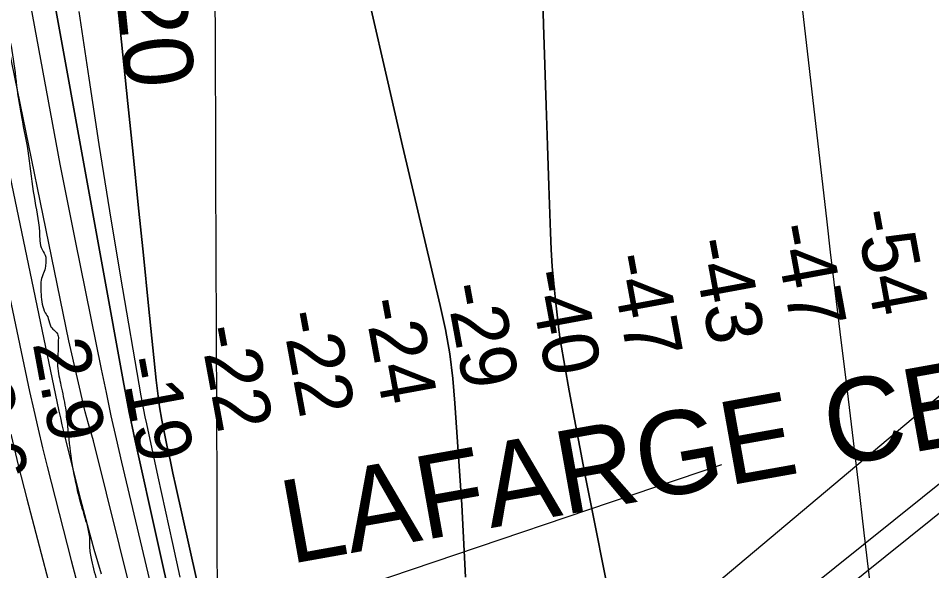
# Model space of a CAD drawing. Extents: x 3392644 to 3430565, y 576657 to 602123.
# Drawn here: x 3412346 to 3413444, y 583022 to 583686 of the extents above; entities that cross this region are included whole.
import ezdxf

# ---------------------------------------------------------------- set-up
doc = ezdxf.new("R2010")
doc.units = 0
for name, color, linetype in [('V-CHAN-NAID', 7, 'Continuous'), ('V-GRID-MAJR', 7, 'Continuous'), ('V-RIVR-EDGE', 7, 'Continuous'), ('V-RIVR-RANG', 7, 'Continuous'), ('V-TOPO-DPTH', 7, 'Continuous'), ('V-TOPO-MAJR', 7, 'Continuous'), ('V-TOPO-MINR', 7, 'Continuous'), ('V-TOPO-MINR-IDEN', 7, 'Continuous'), ('V-TOPO-WATR', 7, 'Continuous'), ('V-UTIL-LINE', 7, 'Continuous')]:
    doc.layers.add(name, color=color, linetype=linetype)

msp = doc.modelspace()

# ---------------------------------------------------------------- linework, layer by layer
at = {"layer": 'V-GRID-MAJR'}
msp.add_spline([(3412589.1, 582101.8), (3412567.1, 588159.5), (3412545, 594220.6), (3412523, 600281.7), (3412523, 600285.2)], degree=3, dxfattribs=at)
at = {"layer": 'V-RIVR-EDGE'}
msp.add_spline([(3412059.2, 585196.3), (3412062.1, 585176.5), (3412061.7, 585167.8), (3412066, 585148), (3412070, 585133.8), (3412072.2, 585119.1), (3412074.7, 585110.4), (3412079.8, 585095.7), (3412081.2, 585089.5), (3412079.7, 585078.5), (3412079.4, 585072.3), (3412081.2, 585067.6), (3412084.5, 585067.2), (3412095.1, 585068.6), (3412098.7, 585067.5), (3412101.3, 585058.4), (3412103.4, 585032.4), (3412101.6, 585030.2), (3412098.6, 585028.4), (3412097.5, 585027.3), (3412097.5, 585024.4), (3412103, 585018.2), (3412107.7, 585007.2), (3412106.9, 584977.9), (3412102.8, 584958.6), (3412103.5, 584940.3), (3412103.5, 584934.1), (3412107.1, 584926.4), (3412113, 584923.8), (3412115.5, 584916.5), (3412114.8, 584908.5), (3412113.7, 584905.5), (3412117.3, 584901.2), (3412119.9, 584893.8), (3412124.2, 584870.8), (3412130.7, 584830.9), (3412135.7, 584804.6), (3412137.9, 584792.5), (3412134.9, 584783.4), (3412138.1, 584748.3), (3412137, 584737.7), (3412137.3, 584723.4), (3412141.7, 584704.8), (3412149.7, 584674.1), (3412155.4, 584639.3), (3412160.8, 584615.2), (3412165.2, 584590.3), (3412166.2, 584579.7), (3412169.1, 584565.1), (3412169.1, 584558.5), (3412167.6, 584554.9), (3412164.3, 584551.9), (3412166.9, 584533.3), (3412168.3, 584519), (3412171.2, 584502.2), (3412177.3, 584467.8), (3412184.2, 584443.7), (3412191.4, 584410), (3412199.7, 584367.6), (3412203.6, 584329.2), (3412206.8, 584289), (3412206.4, 584269.3), (3412208.9, 584247.7), (3412213.6, 584217), (3412216.5, 584210.4), (3412220.9, 584204.5), (3412226.7, 584202.3), (3412230.4, 584203.8), (3412233.3, 584201.6), (3412234.4, 584193.5), (3412234, 584192.1), (3412230.3, 584190.6), (3412233.2, 584174.2), (3412237.9, 584149.7), (3412243.7, 584125.5), (3412251, 584099.5), (3412250.9, 584093.7), (3412249.1, 584083.5), (3412250.2, 584076.1), (3412275.2, 584001.5), (3412285.3, 583961.3), (3412288.9, 583930.6), (3412290.3, 583910.1), (3412289.2, 583900.2), (3412292.1, 583879.4), (3412299.3, 583856.3), (3412308, 583829.3), (3412312.7, 583799.3), (3412319.2, 583750.6), (3412321, 583731.3), (3412329.3, 583686.6), (3412338.7, 583647.1), (3412344.4, 583604.4), (3412350.2, 583567.4), (3412358.8, 583520.6), (3412365.3, 583471.6), (3412371.8, 583429.2), (3412375, 583408), (3412379.4, 583398.8), (3412379.3, 583391.2), (3412379, 583387.9), (3412376.8, 583379.8), (3412374.9, 583375.4), (3412373.4, 583366.7), (3412373.8, 583353.9), (3412378.8, 583331.9), (3412382.5, 583325.3), (3412385.7, 583315.1), (3412394.1, 583305.2), (3412394.5, 583299.7), (3412394.4, 583288), (3412393.7, 583278.5), (3412393.7, 583267.9), (3412397.6, 583244.9), (3412403, 583217.8), (3412407.7, 583175), (3412422.1, 583100.4), (3412429, 583076.7), (3412431.9, 583060.6), (3412431.9, 583051.4), (3412434.4, 583035), (3412441.6, 583007.5), (3412451.4, 582962.9), (3412455.4, 582943.9), (3412459, 582941.3), (3412460.5, 582932.2), (3412468.4, 582890.5), (3412469.1, 582885.4), (3412468.4, 582884.6), (3412464, 582883.9), (3412461.8, 582881), (3412462.1, 582876.6), (3412467.6, 582853.2), (3412470.5, 582841.1), (3412473.7, 582838.2), (3412477, 582835.3), (3412479.9, 582822.5), (3412500.5, 582724.5), (3412513.2, 582674), (3412526.2, 582618), (3412557.1, 582528), (3412580.3, 582453), (3412593.3, 582406.6), (3412604.9, 582372.5), (3412613.6, 582344), (3412619.4, 582324.3), (3412630, 582308.1), (3412635.4, 582288.8), (3412638.3, 582277.4), (3412649.2, 582259.8), (3412659, 582231.7), (3412668.5, 582210.1), (3412681.6, 582191.4), (3412693.6, 582172), (3412707.8, 582126.3), (3412708.4, 582107.6), (3412708, 582102.2)], degree=3, dxfattribs=at)
at = {"layer": 'V-RIVR-RANG'}
msp.add_line((3412054.7, 582765.8), (3413191.7, 583149.7), dxfattribs=at)
at = {"layer": 'V-TOPO-DPTH'}
for points in [[(3412436.8, 583985.3), (3412478.2, 583583.4), (3412484.4, 583522.7), (3412490.6, 583461.9), (3412496.8, 583401.1), (3412503, 583340.4), (3412512, 583251.1), (3412513.9, 583235), (3412516.1, 583218.9), (3412518.8, 583203), (3412521.9, 583187.1), (3412525.3, 583171.2), (3412528.7, 583155.3), (3412532.2, 583139.5), (3412535.7, 583123.6), (3412686.5, 582449.5)], [(3412686.5, 582449.5), (3412535.7, 583123.6), (3412532.2, 583139.5), (3412528.7, 583155.3), (3412525.3, 583171.2), (3412521.9, 583187.1), (3412518.8, 583203), (3412516.1, 583218.9), (3412513.9, 583235), (3412512, 583251.1), (3412503, 583340.4), (3412496.8, 583401.1), (3412490.6, 583461.9), (3412484.4, 583522.7), (3412478.2, 583583.4), (3412436.8, 583985.3)], [(3412748.8, 582102.4), (3412725.9, 582179.9), (3412702.6, 582264.6), (3412668.6, 582394.9), (3412663.5, 582414.8), (3412658.5, 582434.7), (3412653.6, 582454.7), (3412648.9, 582474.7), (3412584.5, 582747.9), (3412566.4, 582825.1), (3412548.6, 582902.5), (3412531, 582979.9), (3412513.7, 583057.3), (3412486.9, 583178.3), (3412483.2, 583195.3), (3412479.7, 583212.3), (3412476.4, 583229.4), (3412473.2, 583246.5), (3412345.3, 583950.1)], [(3412345.3, 583950.1), (3412473.2, 583246.5), (3412476.4, 583229.4), (3412479.7, 583212.3), (3412483.2, 583195.3), (3412486.9, 583178.3), (3412513.7, 583057.3), (3412531, 582979.9), (3412548.6, 582902.5), (3412566.4, 582825.1), (3412584.5, 582747.9), (3412648.9, 582474.7), (3412653.6, 582454.7), (3412658.5, 582434.7), (3412663.5, 582414.8), (3412668.6, 582394.9), (3412702.6, 582264.6), (3412725.9, 582179.9), (3412748.8, 582102.4)], [(3412973.2, 583830.3), (3412977.6, 583678.1), (3412979, 583629.7), (3412980.5, 583581.2), (3412982.1, 583532.8), (3412983.8, 583484.4), (3412985.8, 583428.4), (3412986.8, 583408), (3412988.1, 583387.7), (3412989.8, 583367.3), (3412991.9, 583347.1), (3412995.4, 583315.6), (3412996, 583311.1), (3412996.6, 583306.5), (3412997.3, 583302), (3412998, 583297.5), (3413008.5, 583238.5), (3413014.7, 583204.4), (3413021, 583170.5), (3413027.5, 583136.5), (3413034.2, 583102.6), (3413140.7, 582570)], [(3412973.2, 583830.3), (3412977.6, 583678.1), (3412979, 583629.7), (3412980.5, 583581.2), (3412982.1, 583532.8), (3412983.8, 583484.4), (3412985.8, 583428.4), (3412986.8, 583408), (3412988.1, 583387.7), (3412989.8, 583367.3), (3412991.9, 583347.1), (3412995.4, 583315.6), (3412996, 583311.1), (3412996.6, 583306.5), (3412997.3, 583302), (3412998, 583297.5), (3413008.5, 583238.5), (3413014.7, 583204.4), (3413021, 583170.5), (3413027.5, 583136.5), (3413034.2, 583102.6), (3413140.7, 582570)], [(3412770.3, 583696.4), (3412789.1, 583614.5), (3412808.1, 583532.6), (3412853.5, 583340.9), (3412859.7, 583311.8), (3412864.8, 583282.6), (3412868.5, 583253.2), (3412871.1, 583223.6), (3412879.2, 583101.5), (3412883.8, 583014.7)], [(3412883.8, 583014.7), (3412879.2, 583101.5), (3412871.1, 583223.6), (3412868.5, 583253.2), (3412864.8, 583282.6), (3412859.7, 583311.8), (3412853.5, 583340.9), (3412808.1, 583532.6), (3412789.1, 583614.5), (3412770.3, 583696.4)], [(3412708.5, 582102.3), (3412704.9, 582116.7), (3412663.6, 582281.1), (3412624.8, 582431.1), (3412605.4, 582511.1), (3412570.8, 582654.3), (3412499.1, 582926.9), (3412436.8, 583178.2), (3412430.9, 583198.7), (3412426.6, 583213.2), (3412407.3, 583298.3), (3412328.2, 583683.4)], [(3412708.5, 582102.3), (3412704.9, 582116.7), (3412663.6, 582281.1), (3412624.8, 582431.1), (3412605.4, 582511.1), (3412570.8, 582654.3), (3412499.1, 582926.9), (3412436.8, 583178.2), (3412430.9, 583198.7), (3412426.6, 583213.2), (3412407.3, 583298.3), (3412328.2, 583683.4)], [(3412305.4, 583494.8), (3412360, 583237.5), (3412365, 583214.9), (3412370.1, 583192.4), (3412375.5, 583169.9), (3412381.1, 583147.4), (3412410, 583034.5), (3412430.7, 582955.7), (3412451.9, 582877.1), (3412473.9, 582798.7), (3412496.5, 582720.5), (3412564.9, 582488.3), (3412574.4, 582455.7), (3412583.7, 582422.9), (3412592.7, 582390.1), (3412601.5, 582357.2), (3412610, 582324.3), (3412618.4, 582291.3), (3412626.6, 582258.3), (3412634.7, 582225.2), (3412664.4, 582102.1)]]:
    msp.add_lwpolyline(points, dxfattribs=at)
at = {"layer": 'V-TOPO-MAJR'}
msp.add_lwpolyline([(3413370.1, 583007.5), (3413363, 583067.7), (3413355.9, 583127.9), (3413348.7, 583188.1), (3413341.4, 583248.3), (3413335.6, 583296), (3413331.2, 583332.3), (3413326.8, 583368.7), (3413322.5, 583405), (3413318.3, 583441.3), (3413255.7, 583983.5)], dxfattribs=at)
at = {"layer": 'V-TOPO-MINR'}
for points in [[(3412436.8, 583985.3), (3412478.2, 583583.4), (3412484.4, 583522.7), (3412490.6, 583461.9), (3412496.8, 583401.1), (3412503, 583340.4), (3412512, 583251.1), (3412513.9, 583235), (3412516.1, 583218.9), (3412518.8, 583203), (3412521.9, 583187.1), (3412525.3, 583171.2), (3412528.7, 583155.3), (3412532.2, 583139.5), (3412535.7, 583123.6), (3412686.5, 582449.5)], [(3412345.3, 583950.1), (3412473.2, 583246.5), (3412476.4, 583229.4), (3412479.7, 583212.3), (3412483.2, 583195.3), (3412486.9, 583178.3), (3412513.7, 583057.3), (3412531, 582979.9), (3412548.6, 582902.5), (3412566.4, 582825.1), (3412584.5, 582747.9), (3412648.9, 582474.7), (3412653.6, 582454.7), (3412658.5, 582434.7), (3412663.5, 582414.8), (3412668.6, 582394.9), (3412702.6, 582264.6), (3412725.9, 582179.9), (3412748.8, 582102.4)], [(3412250.5, 583906.5), (3412395.3, 583213.9), (3412397.1, 583205.8), (3412398.9, 583197.6), (3412400.8, 583189.5), (3412402.8, 583181.3), (3412413.6, 583137.7), (3412421.3, 583107.8), (3412429.1, 583077.9), (3412437.3, 583048.2), (3412445.8, 583018.5)], [(3413140.7, 582570), (3413034.2, 583102.6), (3413027.5, 583136.5), (3413021, 583170.5), (3413014.7, 583204.4), (3413008.5, 583238.5), (3412998, 583297.5), (3412997.3, 583302), (3412996.6, 583306.5), (3412996, 583311.1), (3412995.4, 583315.6), (3412991.9, 583347.1), (3412989.8, 583367.3), (3412988.1, 583387.7), (3412986.8, 583408), (3412985.8, 583428.4), (3412983.8, 583484.4), (3412982.1, 583532.8), (3412980.5, 583581.2), (3412979, 583629.7), (3412977.6, 583678.1), (3412973.2, 583830.3)], [(3412345.2, 583788.2), (3412396.4, 583510.6), (3412414.7, 583418.3), (3412446, 583264.2), (3412451.8, 583236.3), (3412457.8, 583208.4), (3412464.1, 583180.5), (3412470.6, 583152.7), (3412524.6, 582924.7), (3412544.1, 582842.6), (3412563.7, 582760.5), (3412583.3, 582678.4), (3412603.1, 582596.4), (3412629.3, 582487.6), (3412636, 582459.9), (3412642.8, 582432.3), (3412649.8, 582404.7), (3412656.8, 582377.1), (3412713.8, 582156.6), (3412728.4, 582102.3)], [(3412419.3, 583693.8), (3412431.1, 583613.9), (3412443.3, 583534.1), (3412456.2, 583454.3), (3412469.4, 583374.7), (3412493.7, 583232.4), (3412495.2, 583223.9), (3412496.8, 583215.4), (3412498.5, 583207), (3412500.3, 583198.6), (3412514, 583135.1), (3412522.8, 583094.9), (3412531.7, 583054.8), (3412540.7, 583014.7)], [(3412770.3, 583696.4), (3412789.1, 583614.5), (3412808.1, 583532.6), (3412853.5, 583340.9), (3412859.7, 583311.8), (3412864.8, 583282.6), (3412868.5, 583253.2), (3412871.1, 583223.6), (3412879.2, 583101.5), (3412883.8, 583014.7)], [(3412305.4, 583494.8), (3412360, 583237.5), (3412365, 583214.9), (3412370.1, 583192.4), (3412375.5, 583169.9), (3412381.1, 583147.4), (3412410, 583034.5), (3412430.7, 582955.7), (3412451.9, 582877.1), (3412473.9, 582798.7), (3412496.5, 582720.5), (3412564.9, 582488.3), (3412574.4, 582455.7), (3412583.7, 582422.9), (3412592.7, 582390.1), (3412601.5, 582357.2), (3412610, 582324.3), (3412618.4, 582291.3), (3412626.6, 582258.3), (3412634.7, 582225.2), (3412664.4, 582102.1)], [(3412337.3, 583186.4), (3412346.8, 583147.6), (3412356.7, 583108.8), (3412442.2, 582781.8), (3412458.3, 582720.7), (3412474.8, 582659.8), (3412491.6, 582598.9), (3412508.7, 582538.1), (3412531.6, 582457.5), (3412537.4, 582437), (3412543.1, 582416.6), (3412548.8, 582396.1), (3412554.4, 582375.7), (3412602.5, 582199.3), (3412628.9, 582102)]]:
    msp.add_lwpolyline(points, dxfattribs=at)
at = {"layer": 'V-TOPO-WATR'}
msp.add_lwpolyline([(3412708.5, 582102.3), (3412704.9, 582116.7), (3412663.6, 582281.1), (3412624.8, 582431.1), (3412605.4, 582511.1), (3412570.8, 582654.3), (3412499.1, 582926.9), (3412436.8, 583178.2), (3412430.9, 583198.7), (3412426.6, 583213.2), (3412407.3, 583298.3), (3412328.2, 583683.4)], dxfattribs=at)
at = {"layer": 'V-UTIL-LINE'}
for p, q in [((3412297.9, 582200.1), (3415100.6, 584449.1)), ((3412328.9, 582189.7), (3415131.6, 584438.8))]:
    msp.add_line(p, q, dxfattribs=at)
msp.add_lwpolyline([(3412089.9, 582100), (3412531, 582457.8), (3414603.6, 584199.2), (3415068.6, 584289.5), (3415163.5, 584253.5), (3416142.9, 584475.3), (3415963.7, 585214)], dxfattribs=at)

# ---------------------------------------------------------------- texts
at = {"layer": 'V-CHAN-NAID'}
msp.add_text('LAFARGE CEMENT (167.9) (2)', height=100, rotation=10.1437, dxfattribs=at).set_placement((3412672.7, 583030.2))
at = {"layer": 'V-RIVR-RANG'}
for s, rotation, p in [('-54', 280.4704, (3413351.5, 583452.6)), ('-47', 280.4704, (3413252.9, 583435.5)), ('-43', 280.4704, (3413154.5, 583418.1)), ('-47', 280.4704, (3413056.2, 583399.6)), ('-40', 280.4704, (3412958.1, 583379.9)), ('-29', 280.4704, (3412859.4, 583364)), ('-24', 280.4704, (3412761, 583346.1)), ('-22', 280.4704, (3412662.1, 583331)), ('-22', 280.4704, (3412563.7, 583313.1)), ('18.6', 280.1883, (3412262.5, 583295.4)), ('2.9', 280.4704, (3412363.6, 583295.4)), ('-19', 280.4704, (3412468.9, 583275.7))]:
    msp.add_text(s, height=67, rotation=rotation, dxfattribs=at).set_placement(p)
at = {"layer": 'V-TOPO-MINR-IDEN'}
msp.add_text('-20', height=83, rotation=275.8819, dxfattribs=at).set_placement((3412460.2, 583758.4))

doc.saveas('drawing.dxf')
